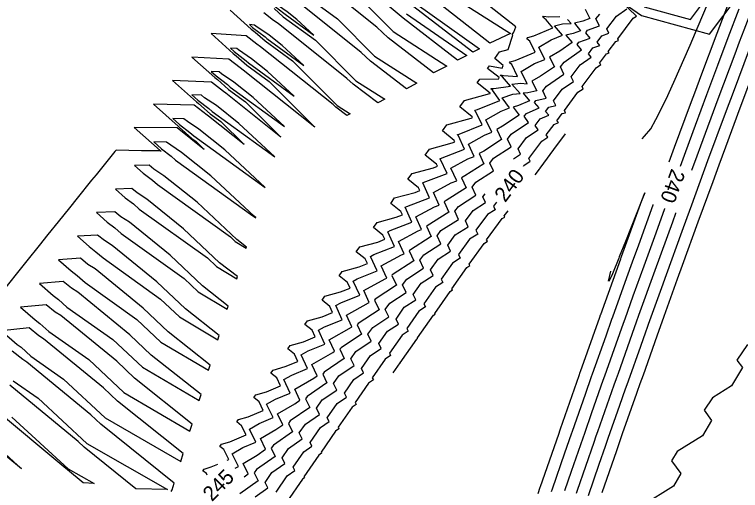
# Model space of a CAD drawing. Extents: x 1160447 to 1162032, y 616022 to 618272.
# Drawn here: x 1160877.4 to 1160997.8, y 616654 to 616733 of the extents above; entities that cross this region are included whole.
import ezdxf

# ---------------------------------------------------------------- set-up
doc = ezdxf.new("R2010")
doc.units = 0
doc.layers.add('D_Contours_Major', color=7, linetype='Continuous')
doc.layers.add('D_Contours_Minor', color=7, linetype='Continuous')

msp = doc.modelspace()

# ---------------------------------------------------------------- linework, layer by layer
at = {"layer": 'D_Contours_Major'}
for points in [[(1160961.84, 616707.8), (1160961.92, 616707.91), (1160962.98, 616708.6), (1160962.76, 616709.06), (1160964.9, 616711.96), (1160965.89, 616712.62), (1160965.64, 616712.97), (1160966.95, 616714.73), (1160967.65, 616715.03), (1160967.38, 616715.33), (1160968.26, 616716.52), (1160968.82, 616716.63), (1160968.63, 616717.02), (1160970.88, 616720.05), (1160971.74, 616720.64), (1160971.57, 616721), (1160973.9, 616724.11), (1160974.67, 616724.65), (1160974.47, 616724.9), (1160975.63, 616726.43), (1160976.09, 616726.58), (1160975.91, 616726.81), (1160977.18, 616728.5), (1160977.62, 616728.67), (1160977.49, 616728.92), (1160980.07, 616732.34), (1160980.58, 616732.7), (1160977.99, 616735.17), (1160981.43, 616732.8), (1160992.71, 616729.7), (1161001.7, 616741.71)], [(1160997.56, 616733.84), (1160995.76, 616729.09), (1160994.05, 616724.51), (1160992.22, 616719.63), (1160990.34, 616714.55), (1160988.71, 616710.17), (1160987.83, 616707.75)], [(1160914.03, 616657.68), (1160914.59, 616657.92), (1160913.55, 616660.04), (1160915.3, 616661.09), (1160917.45, 616661.99), (1160916.4, 616664.15), (1160918, 616665.1), (1160920.31, 616666.06), (1160919.25, 616668.26), (1160920.7, 616669.11), (1160923.17, 616670.13), (1160922.11, 616672.36), (1160923.41, 616673.12), (1160926.04, 616674.19), (1160924.97, 616676.46), (1160926.12, 616677.12), (1160928.92, 616678.25), (1160927.83, 616680.55), (1160928.84, 616681.12), (1160931.8, 616682.31), (1160930.71, 616684.64), (1160931.56, 616685.12), (1160934.68, 616686.36), (1160933.58, 616688.72), (1160934.28, 616689.11), (1160937.57, 616690.41), (1160936.46, 616692.81), (1160937.01, 616693.11), (1160940.46, 616694.46), (1160939.35, 616696.88), (1160939.75, 616697.1), (1160943.36, 616698.5), (1160942.24, 616700.96), (1160942.48, 616701.09), (1160946.27, 616702.54), (1160945.14, 616705.02), (1160945.23, 616705.06), (1160949.18, 616706.58), (1160948.05, 616709), (1160948.02, 616709.02), (1160948.03, 616709.04), (1160948.09, 616709.05), (1160952.09, 616710.61), (1160951, 616712.91), (1160950.89, 616713), (1160950.93, 616713.06), (1160951.16, 616713.12), (1160955.01, 616714.64), (1160953.97, 616716.82), (1160953.77, 616716.98), (1160953.84, 616717.08), (1160954.25, 616717.19), (1160957.93, 616718.67), (1160956.69, 616720.4), (1160956.41, 616720.62), (1160956.47, 616720.71), (1160956.92, 616720.71), (1160959.69, 616721.08), (1160958.36, 616722.6), (1160958.03, 616722.86), (1160958.07, 616722.93), (1160958.54, 616722.84), (1160960.86, 616722.69), (1160959.91, 616724.64), (1160959.54, 616724.95), (1160959.67, 616725.13), (1160960.45, 616725.35), (1160963.79, 616726.71), (1160962.89, 616728.55), (1160962.43, 616728.93), (1160962.6, 616729.16), (1160963.57, 616729.43), (1160966.73, 616730.73), (1160965.61, 616732.1), (1160965.06, 616732.54), (1160965.15, 616732.67), (1160965.99, 616732.59), (1160967.9, 616732.66)], [(1160957.39, 616701.8), (1160956.89, 616701.13), (1160957.16, 616700.56), (1160955.91, 616699.77), (1160953.97, 616697.16), (1160954.26, 616696.53), (1160952.92, 616695.69), (1160951.09, 616693.11), (1160951.36, 616692.5), (1160950.07, 616691.68), (1160948.21, 616689.02), (1160948.47, 616688.47), (1160947.28, 616687.7), (1160945.35, 616684.94), (1160945.58, 616684.43), (1160944.49, 616683.71), (1160942.49, 616680.85), (1160942.7, 616680.39), (1160941.71, 616679.73), (1160939.63, 616676.75), (1160939.82, 616676.34), (1160938.93, 616675.75), (1160936.78, 616672.65), (1160936.95, 616672.3), (1160936.17, 616671.77), (1160933.94, 616668.55), (1160934.08, 616668.25), (1160933.41, 616667.79), (1160931.1, 616664.44), (1160931.22, 616664.19), (1160930.66, 616663.81), (1160928.27, 616660.33), (1160928.36, 616660.14), (1160927.92, 616659.83), (1160925.44, 616656.21), (1160925.51, 616656.07), (1160925.19, 616655.85), (1160922.62, 616652.09)], [(1160985.26, 616700.74), (1160985.24, 616700.69), (1160983.78, 616696.65), (1160981.8, 616691.2), (1160980, 616686.19), (1160978.64, 616682.38), (1160978.4, 616681.7), (1160976.57, 616676.54), (1160975.29, 616672.93), (1160975.02, 616672.19), (1160973.15, 616666.84), (1160971.95, 616663.41), (1160971.69, 616662.66), (1160969.77, 616657.13), (1160968.64, 616653.87)]]:
    msp.add_lwpolyline(points, dxfattribs=at)
at = {"layer": 'D_Contours_Minor'}
for points in [[(1160981.88, 616734.24), (1160989.54, 616732.13), (1160998.52, 616744.15)], [(1160912.69, 616658.98), (1160912.98, 616659.1), (1160912.17, 616660.74), (1160911.49, 616661.27), (1160911.74, 616661.63), (1160913.12, 616662.03), (1160915.83, 616663.17), (1160915.09, 616664.71), (1160914.3, 616665.33), (1160914.59, 616665.74), (1160916.18, 616666.2), (1160918.7, 616667.25), (1160918, 616668.68), (1160917.12, 616669.38), (1160917.45, 616669.84), (1160919.24, 616670.35), (1160921.56, 616671.31), (1160920.93, 616672.65), (1160919.94, 616673.42), (1160920.31, 616673.94), (1160922.3, 616674.51), (1160924.43, 616675.38), (1160923.85, 616676.61), (1160922.77, 616677.46), (1160923.17, 616678.04), (1160925.37, 616678.65), (1160927.31, 616679.44), (1160926.78, 616680.56), (1160925.6, 616681.5), (1160926.04, 616682.13), (1160928.44, 616682.8), (1160930.19, 616683.5), (1160929.72, 616684.52), (1160928.44, 616685.53), (1160928.92, 616686.22), (1160931.51, 616686.93), (1160933.08, 616687.56), (1160932.65, 616688.47), (1160931.28, 616689.56), (1160931.8, 616690.3), (1160934.59, 616691.07), (1160935.97, 616691.61), (1160935.6, 616692.41), (1160934.12, 616693.59), (1160934.69, 616694.38), (1160937.68, 616695.19), (1160938.86, 616695.66), (1160938.54, 616696.35), (1160936.98, 616697.61), (1160937.58, 616698.45), (1160940.76, 616699.31), (1160941.76, 616699.7), (1160941.5, 616700.29), (1160939.83, 616701.62), (1160940.48, 616702.53), (1160943.86, 616703.43), (1160944.67, 616703.74), (1160944.45, 616704.22), (1160942.69, 616705.64), (1160943.37, 616706.59), (1160946.95, 616707.54), (1160947.58, 616707.78), (1160947.41, 616708.15), (1160945.56, 616709.64), (1160946.26, 616710.62), (1160950.05, 616711.64), (1160950.49, 616711.82), (1160950.37, 616712.07), (1160948.43, 616713.64), (1160949.16, 616714.65), (1160953.15, 616715.75), (1160953.41, 616715.85), (1160953.34, 616716), (1160951.31, 616717.64), (1160952.06, 616718.68), (1160956.26, 616719.85), (1160956.34, 616719.88), (1160956.31, 616719.91), (1160954.17, 616721.61), (1160954.63, 616722.25), (1160957.76, 616722.29), (1160957.83, 616722.5), (1160955.89, 616724.01), (1160956.21, 616724.45), (1160958.33, 616724.07), (1160958.47, 616724.51), (1160957.08, 616725.64), (1160957.88, 616726.76), (1160959.33, 616727.16), (1160960.1, 616729.53), (1160959.97, 616729.64), (1160960.27, 616730.06), (1160960.56, 616730.94), (1160948.24, 616740.67)], [(1160981.52, 616712.33), (1160981.94, 616712.77), (1160982.95, 616713.97), (1160983.78, 616715.55), (1160985.5, 616718.89), (1160986.77, 616721.75), (1160989.52, 616727.87), (1160990.84, 616731.02), (1160994.09, 616738.75), (1160994.76, 616740.34), (1160994.79, 616740.34), (1160994.81, 616740.34), (1160995.68, 616740.22), (1160997.61, 616739.61), (1160997.48, 616739.27), (1160996.73, 616737.29), (1160993.9, 616729.82), (1160991.21, 616722.63), (1160990.36, 616720.36), (1160989.48, 616718), (1160986.85, 616710.89), (1160985.95, 616708.44)], [(1160934.49, 616735.94), (1160940.21, 616730.12), (1160949.16, 616724.41), (1160946.95, 616723.28), (1160939.43, 616729.09), (1160937.52, 616730.86), (1160927.06, 616739.27)], [(1160946.41, 616738.27), (1160959.69, 616729.79), (1160956.29, 616728.2), (1160945.3, 616736.82)], [(1161001.2, 616737.79), (1160998.4, 616730.39), (1160997.63, 616728.36), (1160996.89, 616726.4), (1160994.09, 616718.91), (1160991.2, 616711.11), (1160990.58, 616709.45), (1160989.71, 616707.06)], [(1160925.06, 616736.62), (1160931.03, 616732.24), (1160937.13, 616726.06), (1160944.17, 616721.55), (1160942.46, 616720.65), (1160936.5, 616725.22), (1160934.95, 616726.65), (1160924.08, 616735.33)], [(1160942.44, 616733.06), (1160952.46, 616726.18), (1160950.9, 616725.4), (1160941.89, 616732.34), (1160939.6, 616734.31)], [(1160943.85, 616734.91), (1160954.58, 616727.28), (1160953.43, 616726.72), (1160943.45, 616734.39)], [(1160913.22, 616733.69), (1160916.7, 616730.55), (1160917.37, 616730.04), (1160918.98, 616728.57), (1160923.52, 616725.25), (1160930.93, 616717.85), (1160933.09, 616716.47), (1160932.56, 616716.21), (1160930.74, 616717.6), (1160930.29, 616718.02), (1160918.24, 616727.6), (1160917.62, 616728.02), (1160915.86, 616729.42), (1160910.03, 616729.8), (1160913.67, 616726.52), (1160914.22, 616726.1), (1160915.94, 616724.54), (1160919.66, 616721.83), (1160927.25, 616714.28), (1160915.35, 616723.75), (1160914.84, 616724.09), (1160912.97, 616725.58), (1160906.84, 616725.91), (1160910.64, 616722.49), (1160911.08, 616722.16), (1160912.9, 616720.5), (1160915.72, 616718.46), (1160921.63, 616712.6), (1160912.46, 616719.91), (1160912.08, 616720.17), (1160910.09, 616721.75), (1160903.66, 616722.01), (1160907.62, 616718.45), (1160907.92, 616718.22), (1160909.87, 616716.46), (1160911.64, 616715.18), (1160915.5, 616711.38), (1160909.6, 616716.09), (1160909.37, 616716.25), (1160907.24, 616717.94), (1160900.48, 616718.11), (1160904.6, 616714.41), (1160904.76, 616714.29), (1160906.85, 616712.41), (1160907.48, 616711.96), (1160908.91, 616710.55), (1160906.75, 616712.28), (1160906.67, 616712.34), (1160904.4, 616714.15), (1160897.3, 616714.2), (1160901.59, 616710.37), (1160901.59, 616710.37), (1160901.75, 616710.22), (1160901.58, 616710.36), (1160898.48, 616710.33), (1160894.28, 616710.47), (1160894.13, 616710.29), (1160894.09, 616710.24), (1160890.97, 616706.38), (1160890.21, 616705.44), (1160887.8, 616702.46), (1160886.53, 616700.88), (1160884.65, 616698.54), (1160882.97, 616696.45), (1160881.49, 616694.61), (1160879.46, 616692.07), (1160878.35, 616690.68), (1160875.99, 616687.73)], [(1160972.07, 616733.88), (1160972.86, 616732.32), (1160971.69, 616731.87), (1160970.32, 616731.51), (1160971.33, 616730.23), (1160970.12, 616729.83), (1160968.88, 616729.56), (1160969.91, 616728.3), (1160967.87, 616726.89), (1160966.18, 616725.89), (1160966.97, 616724.28), (1160964.7, 616722.73), (1160963.25, 616721.89), (1160964.04, 616720.27), (1160962.59, 616719.96), (1160961.8, 616719.89), (1160962.87, 616718.66), (1160961, 616717.88), (1160960.14, 616717.61), (1160961.12, 616716.25), (1160958.38, 616714.42), (1160957.41, 616713.87), (1160958.2, 616712.23), (1160955.25, 616710.3), (1160954.49, 616709.87), (1160955.28, 616708.2), (1160952.14, 616706.18), (1160951.58, 616705.87), (1160952.37, 616704.17), (1160949.05, 616702.07), (1160948.67, 616701.87), (1160949.46, 616700.14), (1160945.89, 616697.88), (1160945.78, 616697.82), (1160946.56, 616696.1), (1160942.92, 616693.77), (1160942.9, 616693.74), (1160943.67, 616692.06), (1160940.08, 616689.74), (1160940.02, 616689.66), (1160940.77, 616688.02), (1160937.24, 616685.71), (1160937.14, 616685.57), (1160937.89, 616683.97), (1160934.41, 616681.68), (1160934.28, 616681.48), (1160935.01, 616679.92), (1160931.59, 616677.65), (1160931.41, 616677.39), (1160932.13, 616675.87), (1160928.78, 616673.61), (1160928.56, 616673.29), (1160929.26, 616671.81), (1160925.97, 616669.58), (1160925.7, 616669.19), (1160926.39, 616667.75), (1160923.17, 616665.54), (1160922.86, 616665.09), (1160923.53, 616663.69), (1160920.38, 616661.5), (1160920.02, 616660.98), (1160920.67, 616659.62), (1160917.59, 616657.46), (1160917.18, 616656.86), (1160917.82, 616655.55), (1160914.81, 616653.42)], [(1160917.37, 616652.91), (1160919.43, 616654.37), (1160918.99, 616655.27), (1160920.12, 616656.92), (1160922.28, 616658.44), (1160921.82, 616659.39), (1160922.89, 616660.94), (1160925.14, 616662.51), (1160924.66, 616663.5), (1160925.67, 616664.96), (1160928, 616666.57), (1160927.5, 616667.61), (1160928.45, 616668.98), (1160930.87, 616670.62), (1160930.35, 616671.71), (1160931.24, 616673), (1160933.74, 616674.68), (1160933.2, 616675.81), (1160934.04, 616677.02), (1160936.61, 616678.73), (1160936.06, 616679.91), (1160936.84, 616681.03), (1160939.49, 616682.78), (1160938.92, 616684), (1160939.66, 616685.05), (1160942.38, 616686.82), (1160941.79, 616688.08), (1160942.48, 616689.06), (1160945.27, 616690.86), (1160944.67, 616692.17), (1160945.3, 616693.07), (1160948.16, 616694.9), (1160947.55, 616696.25), (1160948.15, 616697.09), (1160951.06, 616698.93), (1160950.44, 616700.3), (1160951.05, 616701.12), (1160953.97, 616702.97), (1160953.35, 616704.29), (1160953.97, 616705.12), (1160956.88, 616706.99), (1160956.27, 616708.28), (1160956.9, 616709.12), (1160959.79, 616711.02), (1160959.19, 616712.26), (1160959.81, 616713.11), (1160962.71, 616715.04), (1160961.97, 616716.07), (1160962.34, 616716.56), (1160964.46, 616717.45), (1160963.66, 616718.37), (1160963.9, 616718.69), (1160965.63, 616719.06), (1160965.05, 616720.27), (1160965.65, 616721.08), (1160968.56, 616723.07), (1160967.98, 616724.26), (1160968.58, 616725.06), (1160971.5, 616727.08), (1160970.74, 616728), (1160971.03, 616728.39), (1160972.91, 616729.02), (1160972.18, 616729.94), (1160972.49, 616730.35), (1160974.44, 616731.1), (1160973.88, 616732.23), (1160974.49, 616733.04)], [(1160920.51, 616733.98), (1160922.01, 616732.6), (1160927.35, 616728.69), (1160934.03, 616721.96), (1160938.84, 616718.89), (1160937.68, 616718.28), (1160933.6, 616721.4), (1160932.56, 616722.36), (1160921.15, 616731.45), (1160920.41, 616731.95), (1160918.76, 616733.26)], [(1160960.19, 616709.03), (1160961.38, 616709.81), (1160960.98, 616710.66), (1160962.36, 616712.53), (1160964.3, 616713.83), (1160963.81, 616714.52), (1160964.64, 616715.65), (1160966.05, 616716.24), (1160965.52, 616716.85), (1160966.08, 616717.61), (1160967.22, 616717.84), (1160966.84, 616718.64), (1160968.27, 616720.57), (1160970.15, 616721.86), (1160969.77, 616722.63), (1160971.24, 616724.59), (1160973.08, 616725.87), (1160972.61, 616726.45), (1160973.33, 616727.41), (1160974.5, 616727.8), (1160974.05, 616728.38), (1160974.84, 616729.43), (1160976.03, 616729.89), (1160975.68, 616730.57), (1160977.28, 616732.69), (1160978.99, 616733.92)], [(1160915.5, 616656.24), (1160916.21, 616656.74), (1160915.37, 616658.45), (1160917.66, 616659.82), (1160919.06, 616660.81), (1160918.21, 616662.56), (1160920.79, 616664.1), (1160921.92, 616664.88), (1160921.05, 616666.67), (1160923.93, 616668.36), (1160924.78, 616668.94), (1160923.9, 616670.78), (1160927.07, 616672.61), (1160927.65, 616673), (1160926.76, 616674.88), (1160930.21, 616676.85), (1160930.52, 616677.06), (1160929.62, 616678.97), (1160933.34, 616681.08), (1160933.4, 616681.12), (1160932.49, 616683.06), (1160936.16, 616685.12), (1160936.28, 616685.17), (1160935.36, 616687.15), (1160938.89, 616689.1), (1160939.17, 616689.21), (1160938.24, 616691.23), (1160941.62, 616693.09), (1160942.06, 616693.26), (1160941.12, 616695.31), (1160944.36, 616697.07), (1160944.96, 616697.3), (1160944.01, 616699.39), (1160947.11, 616701.05), (1160947.86, 616701.34), (1160946.91, 616703.44), (1160949.85, 616705.02), (1160950.77, 616705.37), (1160949.81, 616707.46), (1160952.61, 616708.99), (1160953.68, 616709.41), (1160952.71, 616711.46), (1160955.37, 616712.95), (1160956.6, 616713.43), (1160955.63, 616715.47), (1160958.14, 616716.9), (1160959.52, 616717.46), (1160958.3, 616719.16), (1160960.11, 616719.72), (1160961.28, 616719.87), (1160959.93, 616721.41), (1160961.4, 616721.55), (1160962.45, 616721.48), (1160961.46, 616723.51), (1160963.69, 616724.81), (1160965.38, 616725.5), (1160964.39, 616727.52), (1160966.47, 616728.75), (1160968.32, 616729.51), (1160967.02, 616731.11), (1160968.35, 616731.4), (1160969.74, 616731.45), (1160969.18, 616732.16)], [(1160972.62, 616653.13), (1160974.41, 616658.31), (1160975.45, 616661.3), (1160975.69, 616662), (1160975.92, 616662.64), (1160977.83, 616668.11), (1160978.78, 616670.81), (1160979.05, 616671.56), (1160979.25, 616672.14), (1160981.29, 616677.89), (1160982.15, 616680.31), (1160982.42, 616681.07), (1160982.6, 616681.56), (1160984.78, 616687.65), (1160985.55, 616689.79), (1160988.16, 616697), (1160988.98, 616699.27), (1160989.76, 616701.38), (1160992.45, 616708.73), (1160995.37, 616716.61), (1160995.95, 616718.19), (1160996.5, 616719.65), (1160999.49, 616727.63)], [(1160974.9, 616653.6), (1160977.33, 616660.61), (1160977.38, 616660.75), (1160977.9, 616662.25), (1160978.3, 616663.39), (1160980.66, 616670.12), (1160980.72, 616670.3), (1160981.23, 616671.74), (1160981.74, 616673.18), (1160984.02, 616679.61), (1160984.1, 616679.82), (1160984.58, 616681.16), (1160985.2, 616682.91), (1160987.42, 616689.09), (1160988.24, 616691.37), (1160990.85, 616698.56), (1160993.3, 616705.25), (1160994.32, 616708.02), (1160995.41, 616710.98), (1160997.82, 616717.46), (1161000.08, 616723.5)], [(1160968.75, 616713.14), (1160967.48, 616711.42), (1160967.49, 616711.41), (1160967.45, 616711.38), (1160964.54, 616707.45), (1160964.57, 616707.39), (1160964.44, 616707.31), (1160963.75, 616706.38)], [(1160920.81, 616653.68), (1160922.66, 616656.39), (1160923.9, 616657.26), (1160923.63, 616657.8), (1160925.41, 616660.39), (1160926.75, 616661.32), (1160926.46, 616661.91), (1160928.16, 616664.39), (1160929.61, 616665.38), (1160929.3, 616666.02), (1160930.93, 616668.39), (1160932.47, 616669.44), (1160932.14, 616670.13), (1160933.7, 616672.38), (1160935.34, 616673.49), (1160934.99, 616674.23), (1160936.48, 616676.38), (1160938.22, 616677.54), (1160937.85, 616678.33), (1160939.27, 616680.38), (1160941.1, 616681.58), (1160940.71, 616682.42), (1160942.07, 616684.38), (1160943.98, 616685.63), (1160943.57, 616686.51), (1160944.88, 616688.38), (1160946.87, 616689.66), (1160946.44, 616690.6), (1160947.69, 616692.37), (1160949.76, 616693.7), (1160949.32, 616694.68), (1160950.54, 616696.39), (1160952.66, 616697.73), (1160952.21, 616698.73), (1160953.48, 616700.45), (1160955.56, 616701.76), (1160955.12, 616702.71), (1160955.49, 616703.21)], [(1160964.29, 616653.47), (1160964.62, 616654.48), (1160964.67, 616654.62), (1160967.69, 616663.33), (1160967.93, 616664.03), (1160967.98, 616664.17), (1160971.09, 616673.04), (1160971.27, 616673.57), (1160971.32, 616673.72), (1160974.52, 616682.74), (1160974.65, 616683.1), (1160974.68, 616683.19), (1160977.99, 616692.42), (1160978.06, 616692.61), (1160978.13, 616692.82), (1160981.5, 616702.11), (1160981.97, 616703.38), (1160981.47, 616702.13), (1160978.75, 616695.27), (1160977.74, 616692.73), (1160977.66, 616692.52), (1160976.61, 616689.94), (1160976.17, 616688.98), (1160975.97, 616688.7), (1160976.36, 616690.36)], [(1160940.26, 616673.51), (1160941.38, 616675.12), (1160941.43, 616675.15), (1160941.42, 616675.17), (1160944.14, 616679.08), (1160944.3, 616679.19), (1160944.27, 616679.27), (1160946.9, 616683.05), (1160947.18, 616683.23), (1160947.12, 616683.36), (1160949.68, 616687.01), (1160950.07, 616687.27), (1160949.99, 616687.45), (1160952.46, 616690.98), (1160952.96, 616691.3), (1160952.85, 616691.53), (1160955.31, 616694.98), (1160955.86, 616695.33), (1160955.74, 616695.58), (1160958.33, 616699.09), (1160958.76, 616699.35), (1160958.67, 616699.55), (1160959.29, 616700.39)], [(1160966.5, 616653.81), (1160966.65, 616654.24), (1160968.73, 616660.23), (1160969.81, 616663.35), (1160969.96, 616663.79), (1160972.12, 616669.94), (1160973.15, 616672.88), (1160973.31, 616673.33), (1160975.54, 616679.64), (1160976.52, 616682.4), (1160976.66, 616682.78), (1160979, 616689.3), (1160979.93, 616691.91), (1160980.96, 616694.73), (1160983.37, 616701.4), (1160983.38, 616701.42)], [(1160970.63, 616653.5), (1160970.81, 616654.03), (1160973.57, 616661.98), (1160973.93, 616663.02), (1160974.18, 616663.74), (1160976.9, 616671.5), (1160977.27, 616672.53), (1160977.59, 616673.44), (1160980.27, 616681), (1160980.62, 616681.97), (1160981.01, 616683.07), (1160983.67, 616690.5), (1160986.6, 616698.57), (1160987.11, 616699.98), (1160987.14, 616700.05)], [(1160999, 616678.2), (1160997.26, 616675.57), (1160998.16, 616674.35), (1160996.38, 616671.3), (1160993.18, 616669.35), (1160991.81, 616667.26), (1160993.03, 616665.56), (1160991.55, 616663), (1160987.37, 616660.41), (1160986.38, 616658.9), (1160987.94, 616656.75), (1160986.75, 616654.67), (1160981.58, 616651.45)], [(1160903.39, 616653.78), (1160903.6, 616654.08), (1160903.92, 616655.17), (1160891.73, 616664.97), (1160890.09, 616666.54), (1160879.45, 616675.28), (1160878.81, 616675.68), (1160877.06, 616677.1)], [(1160877.18, 616672.17), (1160881.33, 616669.26), (1160889.41, 616661.77), (1160902.79, 616654.1), (1160897.57, 616654.21), (1160888.96, 616661.16), (1160888, 616662.09), (1160876.65, 616671.43)], [(1160876.98, 616666.14), (1160886.33, 616657.54), (1160890.63, 616655.09), (1160888.84, 616655.23), (1160886.2, 616657.37), (1160885.94, 616657.63), (1160873.86, 616667.6)], [(1160872.53, 616663.09), (1160878.61, 616657.53), (1160871.08, 616663.77)], [(1160909.38, 616656.52), (1160909.27, 616656.76), (1160908.68, 616657.22), (1160908.89, 616657.52), (1160910.07, 616657.86), (1160911.13, 616658.31)]]:
    msp.add_lwpolyline(points, dxfattribs=at)
for points in [[(1160920.32, 616734.99), (1160920.16, 616735.12), (1160919.61, 616735.17), (1160919.96, 616734.85), (1160922.1, 616733.21), (1160922.32, 616733.01), (1160927.05, 616729.54), (1160924.25, 616732.12), (1160922.63, 616733.41)], [(1160917.45, 616731.03), (1160917.21, 616731.22), (1160916.42, 616731.28), (1160916.92, 616730.83), (1160918.98, 616729.25), (1160919.28, 616728.98), (1160925.43, 616724.49), (1160921.81, 616727.82), (1160919.68, 616729.51)], [(1160914.6, 616727.08), (1160914.28, 616727.33), (1160913.23, 616727.4), (1160913.89, 616726.8), (1160915.87, 616725.29), (1160916.24, 616724.95), (1160923.81, 616719.43), (1160919.39, 616723.52), (1160916.75, 616725.62)], [(1160911.76, 616723.12), (1160911.36, 616723.44), (1160910.04, 616723.51), (1160910.86, 616722.77), (1160912.76, 616721.33), (1160913.21, 616720.91), (1160922.2, 616714.38), (1160916.99, 616719.2), (1160913.82, 616721.73)], [(1160908.93, 616719.16), (1160908.44, 616719.55), (1160906.86, 616719.61), (1160907.83, 616718.74), (1160909.64, 616717.37), (1160910.19, 616716.87), (1160920.6, 616709.32), (1160914.62, 616714.87), (1160910.91, 616717.84)], [(1160906.12, 616715.2), (1160905.54, 616715.67), (1160903.68, 616715.71), (1160904.82, 616714.7), (1160906.53, 616713.4), (1160907.16, 616712.83), (1160919.01, 616704.27), (1160912.29, 616710.52), (1160908, 616713.95)], [(1160903.33, 616711.25), (1160902.65, 616711.8), (1160900.51, 616711.81), (1160901.8, 616710.66), (1160903.41, 616709.44), (1160904.14, 616708.78), (1160916.98, 616699.53), (1160917.11, 616699.41), (1160917.43, 616699.21), (1160917.44, 616699.25), (1160917.16, 616699.47), (1160909.98, 616706.16), (1160905.11, 616710.07)], [(1160900.56, 616707.3), (1160899.77, 616707.93), (1160897.34, 616707.91), (1160898.79, 616706.61), (1160900.29, 616705.48), (1160901.13, 616704.73), (1160913.23, 616696.04), (1160914.03, 616695.26), (1160915.85, 616694.16), (1160915.91, 616694.36), (1160914.29, 616695.62), (1160907.71, 616701.79), (1160902.22, 616706.2)], [(1160897.8, 616703.35), (1160896.9, 616704.07), (1160894.18, 616704), (1160895.79, 616702.56), (1160897.17, 616701.53), (1160898.12, 616700.67), (1160909.42, 616692.58), (1160910.95, 616691.11), (1160914.28, 616689.1), (1160914.39, 616689.46), (1160911.44, 616691.77), (1160905.46, 616697.41), (1160899.35, 616702.34)], [(1160895.07, 616699.4), (1160894.05, 616700.22), (1160891.02, 616700.08), (1160892.79, 616698.51), (1160894.05, 616697.56), (1160895.12, 616696.61), (1160905.56, 616689.15), (1160907.87, 616686.95), (1160912.71, 616684.04), (1160912.88, 616684.57), (1160908.6, 616687.94), (1160903.24, 616693.01), (1160896.49, 616698.48)], [(1160892.33, 616695.45), (1160891.2, 616696.36), (1160887.87, 616696.16), (1160889.79, 616694.46), (1160890.94, 616693.59), (1160892.12, 616692.55), (1160901.67, 616685.74), (1160904.79, 616682.78), (1160911.16, 616678.99), (1160911.37, 616679.68), (1160905.77, 616684.1), (1160901.02, 616688.61), (1160893.64, 616694.61)], [(1160889.6, 616691.49), (1160888.35, 616692.5), (1160884.72, 616692.24), (1160886.8, 616690.4), (1160887.84, 616689.62), (1160889.12, 616688.48), (1160897.74, 616682.36), (1160901.71, 616678.6), (1160909.61, 616673.93), (1160909.87, 616674.78), (1160902.94, 616680.27), (1160898.79, 616684.21), (1160890.78, 616690.74)], [(1160886.88, 616687.54), (1160885.51, 616688.64), (1160881.57, 616688.32), (1160883.82, 616686.33), (1160884.73, 616685.65), (1160886.13, 616684.41), (1160893.76, 616679.01), (1160898.64, 616674.41), (1160908.07, 616668.87), (1160908.37, 616669.88), (1160900.12, 616676.44), (1160896.58, 616679.81), (1160887.93, 616686.86)], [(1160884.16, 616683.58), (1160882.68, 616684.78), (1160878.43, 616684.39), (1160880.84, 616682.26), (1160881.62, 616681.68), (1160883.14, 616680.34), (1160889.73, 616675.68), (1160895.56, 616670.21), (1160906.53, 616663.82), (1160906.88, 616664.98), (1160897.32, 616672.61), (1160894.38, 616675.4), (1160885.09, 616682.99)], [(1160881.47, 616679.63), (1160879.86, 616680.93), (1160875.29, 616680.45), (1160877.86, 616678.19), (1160878.51, 616677.72), (1160880.16, 616676.26), (1160885.57, 616672.44), (1160892.49, 616666), (1160905, 616658.76), (1160905.4, 616660.07), (1160894.52, 616668.78), (1160892.21, 616670.99), (1160882.26, 616679.12)]]:
    msp.add_lwpolyline(points, close=True, dxfattribs=at)

# ---------------------------------------------------------------- texts
at = {"layer": 'D_Contours_Major'}
for s, rotation, p in [('240', 53.4562, (1160958.83, 616701.65)), ('240', 249.8722, (1160986.41, 616707.49)), ('245', 45.7543, (1160910.18, 616651.99))]:
    msp.add_text(s, height=2.49, rotation=rotation, dxfattribs=at).set_placement(p)

doc.saveas('drawing.dxf')
